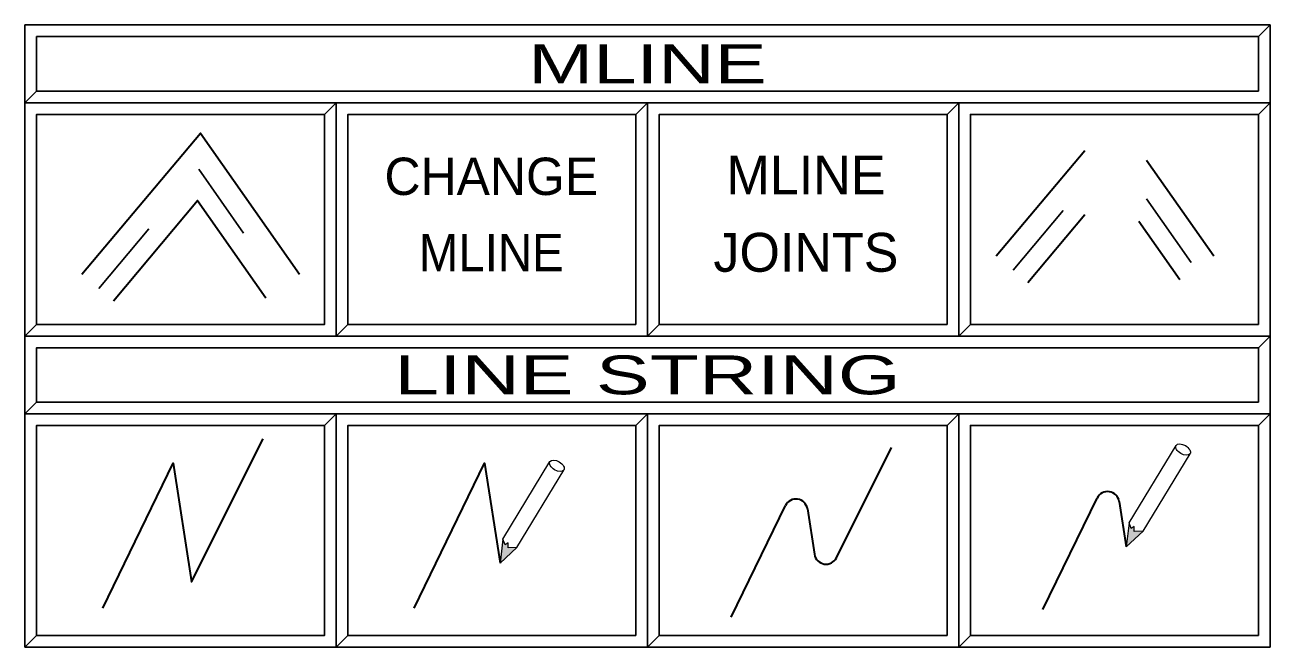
# Model space of a CAD drawing. Extents: x 95906.8 to 95923.6, y 90964.8 to 90972.8.
# Drawn here: x 95908.935 to 95910.535, y 90966.989 to 90967.789 of the extents above; entities that cross this region are included whole.
import ezdxf
from ezdxf.enums import TextEntityAlignment as Align

# ---------------------------------------------------------------- set-up
doc = ezdxf.new("R2010")
doc.units = 0
doc.header["$LTSCALE"] = 0.019
doc.linetypes.add('DOT_DASHED', pattern=[7.7, 5, -1.2, 0.3, -1.2])
for name, color, linetype, lineweight in [('1', 7, 'Continuous', 25), ('11', 7, 'Continuous', 25), ('12', 7, 'Continuous', 25), ('17', 7, 'Continuous', 25), ('2', 7, 'Continuous', 13), ('3', 7, 'Continuous', 25), ('6', 7, 'Continuous', 35), ('7', 7, 'Continuous', 35)]:
    doc.layers.add(name, color=color, linetype=linetype, lineweight=lineweight)

msp = doc.modelspace()

# ---------------------------------------------------------------- hatches: boundary and pattern name
at = {"layer": '6'}
for points in [[(95910.3535, 90967.1484), (95910.3497, 90967.1176), (95910.3715, 90967.1376), (95910.3601, 90967.1372), (95910.3601, 90967.1438), (95910.3562, 90967.1412)], [(95909.5489, 90967.1275), (95909.5451, 90967.0967), (95909.5669, 90967.1167), (95909.5555, 90967.1163), (95909.5555, 90967.1229), (95909.5516, 90967.1203)]]:
    msp.add_hatch(color=256, dxfattribs=at).paths.add_polyline_path(points)

# ---------------------------------------------------------------- linework, layer by layer
at = {"layer": '1'}
for points in [[(95908.9346, 90967.6887), (95910.5346, 90967.6887), (95910.5346, 90967.7887), (95908.9346, 90967.7887)], [(95908.9346, 90967.3887), (95909.3346, 90967.3887), (95909.3346, 90967.6887), (95908.9346, 90967.6887)], [(95909.3346, 90967.3887), (95909.7346, 90967.3887), (95909.7346, 90967.6887), (95909.3346, 90967.6887)], [(95909.7346, 90967.3887), (95910.1346, 90967.3887), (95910.1346, 90967.6887), (95909.7346, 90967.6887)], [(95910.1346, 90967.3887), (95910.5346, 90967.3887), (95910.5346, 90967.6887), (95910.1346, 90967.6887)], [(95908.9346, 90967.2887), (95910.5346, 90967.2887), (95910.5346, 90967.3887), (95908.9346, 90967.3887)], [(95908.9346, 90966.9887), (95909.3346, 90966.9887), (95909.3346, 90967.2887), (95908.9346, 90967.2887)], [(95909.3346, 90966.9887), (95909.7346, 90966.9887), (95909.7346, 90967.2887), (95909.3346, 90967.2887)], [(95909.7346, 90966.9887), (95910.1346, 90966.9887), (95910.1346, 90967.2887), (95909.7346, 90967.2887)], [(95910.1346, 90966.9887), (95910.5346, 90966.9887), (95910.5346, 90967.2887), (95910.1346, 90967.2887)]]:
    msp.add_lwpolyline(points, close=True, dxfattribs=at)
at = {"layer": '11'}
for points in [[(95908.9496, 90967.4037), (95909.3196, 90967.4037), (95909.3196, 90967.6737), (95908.9496, 90967.6737)], [(95909.3496, 90967.4037), (95909.7196, 90967.4037), (95909.7196, 90967.6737), (95909.3496, 90967.6737)], [(95909.7496, 90967.4037), (95910.1196, 90967.4037), (95910.1196, 90967.6737), (95909.7496, 90967.6737)], [(95910.1496, 90967.4037), (95910.5196, 90967.4037), (95910.5196, 90967.6737), (95910.1496, 90967.6737)], [(95909.3496, 90967.0037), (95909.7196, 90967.0037), (95909.7196, 90967.2737), (95909.3496, 90967.2737)], [(95909.7496, 90967.0037), (95910.1196, 90967.0037), (95910.1196, 90967.2737), (95909.7496, 90967.2737)], [(95910.1496, 90967.0037), (95910.5196, 90967.0037), (95910.5196, 90967.2737), (95910.1496, 90967.2737)]]:
    msp.add_lwpolyline(points, close=True, dxfattribs=at)
at = {"layer": '12'}
msp.add_lwpolyline([(95908.9496, 90967.0037), (95909.3196, 90967.0037), (95909.3196, 90967.2737), (95908.9496, 90967.2737)], close=True, dxfattribs=at)
at = {"layer": '17'}
for points in [[(95908.9496, 90967.7037), (95910.5196, 90967.7037), (95910.5196, 90967.7737), (95908.9496, 90967.7737)], [(95908.9496, 90967.3037), (95910.5196, 90967.3037), (95910.5196, 90967.3737), (95908.9496, 90967.3737)]]:
    msp.add_lwpolyline(points, close=True, dxfattribs=at)
at = {"layer": '2'}
for points in [[(95908.9346, 90967.7887), (95908.9346, 90967.6887), (95908.9496, 90967.7037), (95908.9496, 90967.7737), (95910.5196, 90967.7737), (95910.5346, 90967.7887)], [(95908.9346, 90967.6887), (95908.9346, 90967.3887), (95908.9496, 90967.4037), (95908.9496, 90967.6737), (95909.3196, 90967.6737), (95909.3346, 90967.6887)], [(95909.3346, 90967.6887), (95909.3346, 90967.3887), (95909.3496, 90967.4037), (95909.3496, 90967.6737), (95909.7196, 90967.6737), (95909.7346, 90967.6887)], [(95909.7346, 90967.6887), (95909.7346, 90967.3887), (95909.7496, 90967.4037), (95909.7496, 90967.6737), (95910.1196, 90967.6737), (95910.1346, 90967.6887)], [(95910.1346, 90967.6887), (95910.1346, 90967.3887), (95910.1496, 90967.4037), (95910.1496, 90967.6737), (95910.5196, 90967.6737), (95910.5346, 90967.6887)], [(95908.9346, 90967.3887), (95908.9346, 90967.2887), (95908.9496, 90967.3037), (95908.9496, 90967.3737), (95910.5196, 90967.3737), (95910.5346, 90967.3887)], [(95908.9346, 90967.2887), (95908.9346, 90966.9887), (95908.9496, 90967.0037), (95908.9496, 90967.2737), (95909.3196, 90967.2737), (95909.3346, 90967.2887)], [(95909.3346, 90967.2887), (95909.3346, 90966.9887), (95909.3496, 90967.0037), (95909.3496, 90967.2737), (95909.7196, 90967.2737), (95909.7346, 90967.2887)], [(95909.7346, 90967.2887), (95909.7346, 90966.9887), (95909.7496, 90967.0037), (95909.7496, 90967.2737), (95910.1196, 90967.2737), (95910.1346, 90967.2887)], [(95910.1346, 90967.2887), (95910.1346, 90966.9887), (95910.1496, 90967.0037), (95910.1496, 90967.2737), (95910.5196, 90967.2737), (95910.5346, 90967.2887)]]:
    msp.add_lwpolyline(points, close=True, dxfattribs=at)
at = {"layer": '3'}
for points in [[(95908.9346, 90967.6887), (95910.5346, 90967.6887), (95910.5346, 90967.7887), (95910.5196, 90967.7737), (95910.5196, 90967.7037), (95908.9496, 90967.7037)], [(95908.9346, 90967.3887), (95909.3346, 90967.3887), (95909.3346, 90967.6887), (95909.3196, 90967.6737), (95909.3196, 90967.4037), (95908.9496, 90967.4037)], [(95909.3346, 90967.3887), (95909.7346, 90967.3887), (95909.7346, 90967.6887), (95909.7196, 90967.6737), (95909.7196, 90967.4037), (95909.3496, 90967.4037)], [(95909.7346, 90967.3887), (95910.1346, 90967.3887), (95910.1346, 90967.6887), (95910.1196, 90967.6737), (95910.1196, 90967.4037), (95909.7496, 90967.4037)], [(95910.1346, 90967.3887), (95910.5346, 90967.3887), (95910.5346, 90967.6887), (95910.5196, 90967.6737), (95910.5196, 90967.4037), (95910.1496, 90967.4037)], [(95908.9346, 90967.2887), (95910.5346, 90967.2887), (95910.5346, 90967.3887), (95910.5196, 90967.3737), (95910.5196, 90967.3037), (95908.9496, 90967.3037)], [(95908.9346, 90966.9887), (95909.3346, 90966.9887), (95909.3346, 90967.2887), (95909.3196, 90967.2737), (95909.3196, 90967.0037), (95908.9496, 90967.0037)], [(95909.3346, 90966.9887), (95909.7346, 90966.9887), (95909.7346, 90967.2887), (95909.7196, 90967.2737), (95909.7196, 90967.0037), (95909.3496, 90967.0037)], [(95909.7346, 90966.9887), (95910.1346, 90966.9887), (95910.1346, 90967.2887), (95910.1196, 90967.2737), (95910.1196, 90967.0037), (95909.7496, 90967.0037)], [(95910.1346, 90966.9887), (95910.5346, 90966.9887), (95910.5346, 90967.2887), (95910.5196, 90967.2737), (95910.5196, 90967.0037), (95910.1496, 90967.0037)]]:
    msp.add_lwpolyline(points, close=True, dxfattribs=at)
at = {"layer": '6'}
for p, q in [((95910.1827, 90967.4916), (95910.2965, 90967.6273)), ((95910.376, 90967.6147), (95910.4622, 90967.4916)), ((95910.2233, 90967.4576), (95910.2965, 90967.5449)), ((95910.3661, 90967.5365), (95910.4188, 90967.4612)), ((95909.9774, 90967.1036), (95910.0481, 90967.2452)), ((95909.8421, 90967.0274), (95909.9118, 90967.1707)), ((95910.2427, 90967.037), (95910.3124, 90967.1803)), ((95910.3407, 90967.176), (95910.3497, 90967.1176)), ((95909.9401, 90967.1664), (95909.9491, 90967.108))]:
    msp.add_line(p, q, dxfattribs=at)
at = {"layer": '6', "linetype": 'DOT_DASHED', "lineweight": 25}
for p, q in [((95910.2045, 90967.4733), (95910.2965, 90967.583)), ((95910.376, 90967.5651), (95910.4389, 90967.4753))]:
    msp.add_line(p, q, dxfattribs=at)
at = {"layer": '6', "lineweight": 13}
for p, q in [((95910.3535, 90967.1484), (95910.4138, 90967.2481)), ((95910.3715, 90967.1376), (95910.4318, 90967.2373)), ((95909.5489, 90967.1275), (95909.6092, 90967.2272)), ((95909.5669, 90967.1167), (95909.6272, 90967.2164))]:
    msp.add_line(p, q, dxfattribs=at)
at = {"layer": '6'}
for points in [[(95909.0079, 90967.4681), (95909.1602, 90967.6497), (95909.2874, 90967.4681)], [(95909.0485, 90967.4341), (95909.1564, 90967.5628), (95909.244, 90967.4377)], [(95909.0346, 90967.0387), (95909.1252, 90967.225), (95909.1488, 90967.0728), (95909.2406, 90967.2565)], [(95909.4346, 90967.0387), (95909.5252, 90967.225), (95909.5451, 90967.0967)]]:
    msp.add_lwpolyline(points, dxfattribs=at)
at = {"layer": '6', "linetype": 'DOT_DASHED', "lineweight": 25}
msp.add_lwpolyline([(95909.0297, 90967.4498), (95909.1582, 90967.603), (95909.2641, 90967.4518)], dxfattribs=at)
at = {"layer": '6', "lineweight": 13}
for points in [[(95910.3535, 90967.1484), (95910.3497, 90967.1176), (95910.3715, 90967.1376), (95910.3601, 90967.1372), (95910.3601, 90967.1438), (95910.3562, 90967.1412)], [(95909.5489, 90967.1275), (95909.5451, 90967.0967), (95909.5669, 90967.1167), (95909.5555, 90967.1163), (95909.5555, 90967.1229), (95909.5516, 90967.1203)]]:
    msp.add_lwpolyline(points, close=True, dxfattribs=at)
at = {"layer": '6'}
for centre, start, end in [((95910.3258, 90967.1737), 8.8599, 154.0466), ((95909.9253, 90967.1641), 8.8599, 154.0466), ((95909.964, 90967.1103), 188.7687, 333.435)]:
    msp.add_arc(centre, 0.015, start, end, dxfattribs=at)
at = {"layer": '6', "lineweight": 13}
for centre in [(95910.4228, 90967.2427), (95909.6182, 90967.2218)]:
    msp.add_ellipse(centre, major_axis=(-0.009, 0.0054), ratio=0.555562, dxfattribs=at)

# ---------------------------------------------------------------- texts
at = {"layer": '6'}
for s, height, p in [('CHANGE', 0.048, (95909.5339, 90967.57)), ('MLINE', 0.04999, (95909.9382, 90967.5707)), ('JOINTS', 0.04999, (95909.9382, 90967.4713))]:
    msp.add_text(s, height=height, dxfattribs=at).set_placement(p, align=Align.CENTER)
at = {"layer": '6', "width": 0.95}
msp.add_text('MLINE', height=0.048, dxfattribs=at).set_placement((95909.5339, 90967.472), align=Align.CENTER)
at = {"layer": '7'}
for s, width, p in [('         MLINE         ', 1.5, (95909.7345, 90967.7137)), ('      LINE STRING      ', 1.55, (95909.7345, 90967.3137))]:
    msp.add_text(s, height=0.04999, dxfattribs=dict(at, width=width)).set_placement(p, align=Align.CENTER)

doc.saveas('drawing.dxf')
